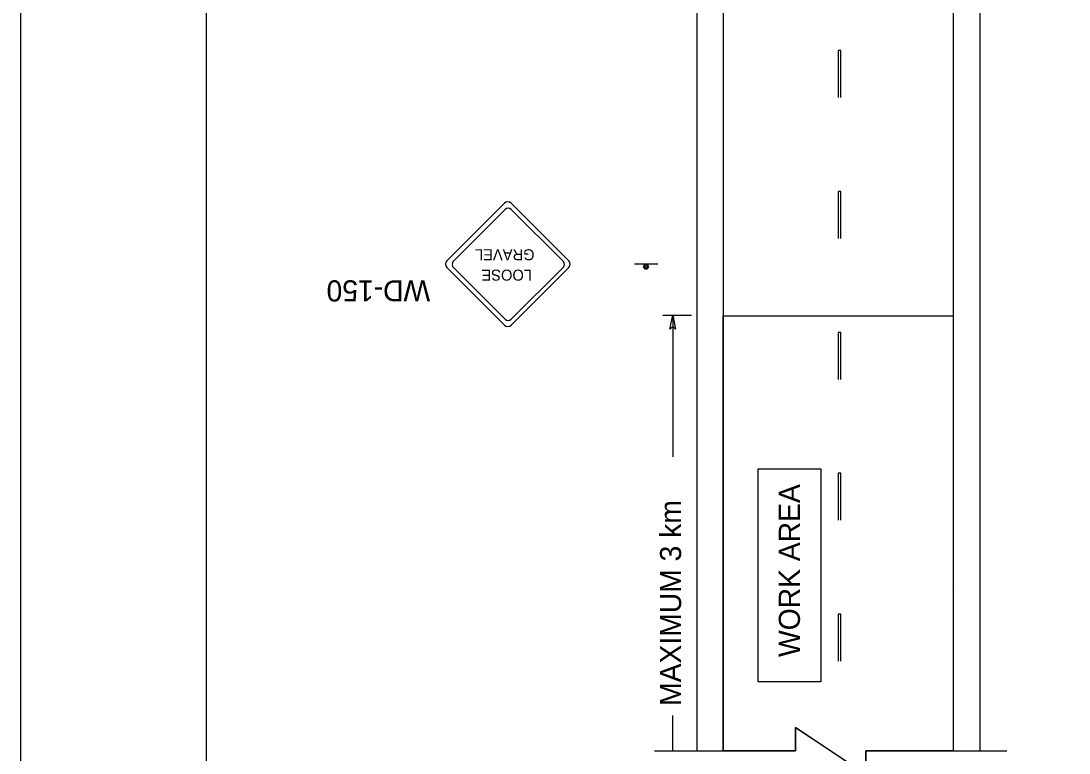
# Model space of a CAD drawing. Extents: x 1342 to 1558, y 178 to 457.
# Drawn here: x 1342.3 to 1450.3, y 306.1 to 381.5 of the extents above; entities that cross this region are included whole.
import ezdxf

# ---------------------------------------------------------------- set-up
doc = ezdxf.new("R2010")
doc.units = 0
for name, color, linetype in [('Level 10', 7, 'Continuous'), ('Level 2', 7, 'Continuous'), ('Level 20', 7, 'Continuous'), ('Level 44', 7, 'Continuous'), ('Level 60', 7, 'Continuous')]:
    doc.layers.add(name, color=color, linetype=linetype)

msp = doc.modelspace()

# ---------------------------------------------------------------- linework, layer by layer
at = {"layer": 'Level 10'}
for p, q in [((1411.92, 441.5), (1411.92, 306.32)), ((1414.64, 441.5), (1414.64, 306.32)), ((1438.35, 441.5), (1438.35, 331.9)), ((1441.09, 441.5), (1441.09, 306.32)), ((1408.42, 351.22), (1411.37, 351.22)), ((1409.44, 351.22), (1409.44, 336.63)), ((1414.64, 351.15), (1438.35, 351.15)), ((1438.35, 331.9), (1438.35, 306.32)), ((1438.84, 323.13), (1438.84, 323.12)), ((1409.44, 306.32), (1409.44, 309.97))]:
    msp.add_line(p, q, dxfattribs=at)
for points in [[(1409.44, 351.22), (1409.74, 349.77), (1409.44, 350.01), (1409.14, 349.77)], [(1414.64, 351.15), (1438.35, 351.15), (1438.35, 306.32), (1429.35, 306.32), (1429.35, 303.91), (1422.1, 308.74), (1422.1, 306.32), (1414.64, 306.32)], [(1418.24, 335.39), (1424.71, 335.39), (1424.71, 313.43), (1418.24, 313.43)]]:
    msp.add_lwpolyline(points, close=True, dxfattribs=at)
at = {"layer": 'Level 2'}
for p, q in [((1426.48, 378.46), (1426.48, 373.62)), ((1426.77, 378.46), (1426.48, 378.46)), ((1426.77, 373.62), (1426.77, 378.46)), ((1426.48, 363.94), (1426.48, 359.11)), ((1426.77, 363.94), (1426.48, 363.94)), ((1426.77, 359.11), (1426.77, 363.94)), ((1426.48, 349.43), (1426.48, 344.59)), ((1426.77, 349.43), (1426.48, 349.43)), ((1426.77, 344.59), (1426.77, 349.43)), ((1426.48, 334.92), (1426.48, 330.08)), ((1426.77, 334.92), (1426.48, 334.92)), ((1426.77, 330.08), (1426.77, 334.92)), ((1426.48, 320.4), (1426.48, 315.56)), ((1426.77, 320.4), (1426.48, 320.4)), ((1426.77, 315.56), (1426.77, 320.4))]:
    msp.add_line(p, q, dxfattribs=at)
at = {"layer": 'Level 20'}
msp.add_lwpolyline([(1407.58, 306.32), (1422.1, 306.32), (1422.1, 308.74), (1425.72, 306.32), (1429.35, 303.91), (1429.35, 306.32), (1443.87, 306.32)], dxfattribs=at)
at = {"layer": 'Level 44'}
for p, q in [((1392.1, 362.76), (1386.17, 356.82)), ((1386.84, 356.76), (1392.17, 362.1)), ((1398.74, 356.82), (1392.8, 362.76)), ((1392.8, 362.1), (1398.15, 356.76)), ((1398.74, 356.82), (1398.74, 356.82)), ((1407.91, 356.45), (1405.49, 356.45)), ((1386.17, 356.12), (1392.1, 350.19)), ((1392.17, 350.79), (1386.84, 356.12)), ((1392.8, 350.19), (1398.74, 356.12)), ((1398.15, 356.12), (1392.8, 350.79))]:
    msp.add_line(p, q, dxfattribs=at)
for radius in [0.242, 0.121]:
    msp.add_circle((1406.69, 356.18), radius, dxfattribs=at)
for centre, radius, start, end in [((1392.45, 362.4), 0.497, 45, 135), ((1392.49, 361.78), 0.447, 45, 135), ((1386.52, 356.47), 0.497, 135, 225), ((1387.15, 356.44), 0.447, 135, 225), ((1397.83, 356.44), 0.447, 315, 45), ((1398.39, 356.47), 0.497, 315, 45), ((1392.45, 350.54), 0.497, 225, 315), ((1392.49, 351.1), 0.447, 225, 315)]:
    msp.add_arc(centre, radius, start, end, dxfattribs=at)
at = {"layer": 'Level 60'}
for points in [[(1342.28, 456.92), (1558.28, 456.92), (1558.28, 177.92), (1342.28, 177.92)], [(1361.41, 446.11), (1548.28, 446.11), (1548.28, 188.73), (1361.41, 188.73)]]:
    msp.add_lwpolyline(points, close=True, dxfattribs=at)

# ---------------------------------------------------------------- texts
at = {"layer": 'Level 10'}
for s, height, rotation, p in [('GRAVEL', 1.131, 180, (1395.2, 358)), ('LOOSE', 1.131, 180, (1394.94, 355.9)), ('WD-150', 2.177, 180, (1384.45, 354.8)), ('WORK AREA', 2.178, 90, (1422.55, 316))]:
    msp.add_text(s, height=height, rotation=rotation, dxfattribs=at).set_placement(p)
at = {"layer": 'Level 60'}
msp.add_text('MAXIMUM 3 km', height=2.178, rotation=90, dxfattribs=at).set_placement((1410.31, 310.96))

doc.saveas('drawing.dxf')
